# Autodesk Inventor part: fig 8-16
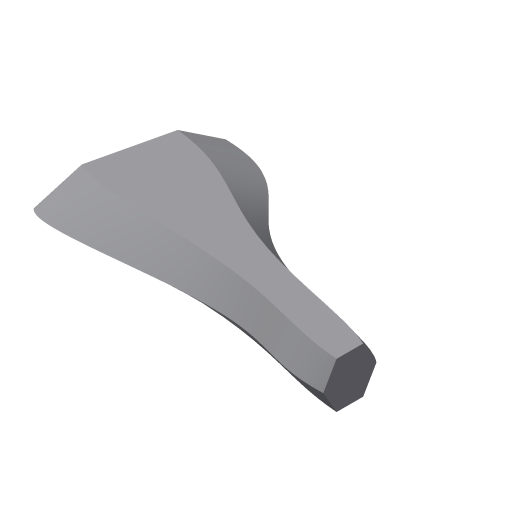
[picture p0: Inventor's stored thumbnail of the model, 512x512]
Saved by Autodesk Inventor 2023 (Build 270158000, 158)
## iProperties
Created: 2004-05
Part Number: fig 8-16
Document SubType Name: Modeling
Designer: CADCIM Technologies
Manufacturer: Standard
Standards Organization: Custom
Density: 1 g/cm^3
Material: Generic
Appearance: Default
Author: CADCIM Technologies
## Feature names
1. Sweep7
## Parameters: d6 = 0, d7 = 0
